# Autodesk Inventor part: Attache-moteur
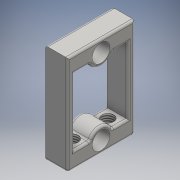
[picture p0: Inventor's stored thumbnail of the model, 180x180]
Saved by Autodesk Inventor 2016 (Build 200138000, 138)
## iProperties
Created: 2018-03
Part Number: Attache-moteur
Material: Générique
Document SubType Name: Modeling
Designer: Bruno
Density: 1 g/cm^3
Appearance: Par défaut
Author: Bruno
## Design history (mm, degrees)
sketch "Esquisse1"
  geometry: L1 (0, 0)-(15, 0); L2 (15, 0)-(15, -11.15); L3 (15, -22.3)-(0, -22.3); L4 (0, -11.15)-(0, 0); L5 (1.5, -3.65)-(1.5, -11.15); L6 (1.5, -18.65)-(13.5, -18.65); L7 (13.5, -11.15)-(13.5, -3.65); L8 (13.5, -3.65)-(10.324, -3.65); L9 (4.676, -3.65)-(1.5, -3.65); L10 (7.5, -22.3)-(7.5, -18.65); L11 (7.5, -11.136)-(7.5, 2.816); L12 (15, -11.15)-(13.5, -11.15); L13 (1.5, -11.15)-(0, -11.15); L14 (1.5, -11.15)-(13.5, -11.15); C1 r 2 at (7.5, -2.636); A1 r 2.705 centre (7.5, -2.636) between (5.116, -3.914) and (9.884, -3.914); A2 r 0.5 centre (4.676, -4.15) between (5.116, -3.914) and (4.676, -3.65); A3 r 0.5 centre (10.324, -4.15) between (10.324, -3.65) and (9.884, -3.914); 2 further points
  constraints: 28 end point, 8 point on circle, 5 horizontal, 5 parallel, 4 centre point, 4 perpendicular, 4 tangent, 3 point on line, 2 midpoint, 2 vertical, 1 coincident, 1 equal radius
  dimensions: "d0" = 15 distance of L3.start L3.end; "d1" = 22.3 distance of L1.end L3.start; "d3" = 12 distance between parallel lines of L5 L7; "d4" = 3.65 distance between parallel lines of L3 L6; "d5" = 1.5 distance between parallel lines of L2 L7; "d6" = 4 diameter of C1; "d7" = 0.5 radius of A2; "d21" = 8.5 distance of L11.start C1.centre
extrude "Extrusion1" new body sketch "Esquisse1" distance "d9" = 5; taper "d10" = 0 deg
mirror "Symétrie1"
sketch "Esquisse2"
  geometry: L1 (0, 0)-(0, 15) reference; L2 (0, 15)-(-5, 15) reference; L3 (-5, 15)-(-5, 0) reference; L4 (0, 0)-(-5, 0) reference; C1 r 1.35 at (-2.5, 11.5); 1 further point
  constraints: 1 centre point
  dimensions: "d11" = 2.7 diameter of C1; "d12" = 3.5 distance from line of L2 C1.centre
extrude "Extrusion2" cut sketch "Esquisse2" distance "d13" = 8; taper "d14" = 0 deg
feature "Filetage1" dims "d15" = 10, "d16" = 0
pattern_linear "Réseau rectangulaire1" dims "d19" = 8
fillet "Congé1" dims "d20" = 0.5
node "Solide1"
node "Boucle projetée1"
other parameters: "d2" = 15, "d8" = 11.15
